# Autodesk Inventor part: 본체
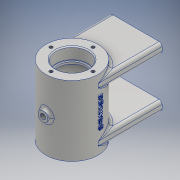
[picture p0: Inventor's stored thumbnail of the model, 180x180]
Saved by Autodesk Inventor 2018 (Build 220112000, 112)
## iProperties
Created: 2020-07
Part Number: 본체
Material: 알루미늄 6061
Document SubType Name: Modeling
Designer: home
Density: 2.7 g/cm^3
Appearance: 알루미늄 - 평지
Mass: 305.056 g
Surface Area: 358.163 cm^2
Volume: 112.984 cm^3
Author: home
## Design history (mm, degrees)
sketch "스케치1"
  geometry: L1 (16, 35)-(16, 23); L2 (16, 23)-(14, 23); L3 (14, 23)-(14, 21); L4 (14, 21)-(21, 21); L5 (21, 21)-(21, -21); L6 (21, -21)-(14, -21); L7 (14, -21)-(14, -23); L8 (14, -23)-(16, -23); L9 (16, -23)-(16, -35); L10 (0, -35)-(0, 35); L11 (16, 35)-(26, 35); L12 (26, 35)-(26, -35); L13 (26, -35)-(16, -35); 3 further points
  constraints: 26 end point, 8 perpendicular, 2 coincident, 2 horizontal, 2 point on line, 2 vertical, 1 midpoint
  dimensions: "d2" = 2 distance of L2.end L3.end; "d4" = 42 distance of L4.end L5.end; "d5" = 2 distance of L6.end L7.end; "d6" = 12 distance of L8.end L9.end; "d8" = 70 distance of L10.start L10.end; "d11" = 32 diameter of L1 L10; "d12" = 52 diameter of L12 L10; "d13" = 42 diameter of L5 L10; "d14" = 10 distance of L12.end L9.end; "d15" = 2 distance of L7.end L8.end; "d16" = 70 distance between parallel lines of L13 L11; "d17" = 35 distance from line of point (0, 0) L11
revolve "회전1" sketch "스케치1" stored, may be unused: angle "d18" = 90 deg
node "작업 평면1"
sketch "스케치2"
  geometry: 1 further point
sketch "스케치3"
  geometry: L1 (-26, -30)-(26, -30); L2 (26, -30)-(26, -20); L3 (26, -20)-(-26, -20); L4 (-26, -20)-(-26, -30); L5 (-26, 35)-(26, 35) reference; L6 (-26, -35)-(26, -35) reference; L7 (-26, 35)-(-26, -35) reference; 1 further point
  constraints: 8 end point, 2 parallel, 1 horizontal, 1 perpendicular
  dimensions: "d20" = 52 distance of L3.end L2.end; "d21" = 10 distance of L2.end L1.end; "d22" = 20 distance from line of L3 point (0, 0); "d23" = 0 distance between parallel lines of L4 L7
extrude "돌출1" join sketch "스케치3" stored distance "d24" = 10; taper "d25" = 0 deg
sketch "스케치4" dims "d26" = 42
  geometry: 3 further points
  constraints: 1 coincident, 1 vertical alignment, 2 other
hole "구멍1" sketch "스케치4" at (0, -21) diameter "d27" = 3.242; stored, may be unused: countersink angle "d31" = 90 deg, drill point angle "d33" = 118 deg; dims "d28" = 8, "d29" = 4, "d30" = 2, "d32" = 10
node "작업 평면2"
sketch "스케치6"
  geometry: C1 r 5 at (0, 0); 1 further point
  constraints: 1 centre point, 1 coincident
  dimensions: "d38" = 10 diameter of C1
extrude "돌출2" join sketch "스케치6" stored distance "d39" = 10 (= d38); taper "d40" = 0 deg
sketch "스케치7"
  geometry: 1 further point
hole "구멍2" sketch "스케치7" at (0, 0) diameter "d41" = 5.188; stored, may be unused: countersink angle "d45" = 90 deg, drill point angle "d47" = 118 deg; dims "d42" = 12, "d43" = 4, "d44" = 2, "d46" = 16
node "작업 평면4"
sketch "스케치11"
  geometry: L1 (-26, -35)-(26, -35) reference; L2 (0, -14.175)-(0, -3.309); L3 (0, -3.309)-(36.054, -3.309); L4 (36.054, -3.309)-(36.054, -14.175); L5 (36.054, -14.175)-(0, -14.175); 1 further point
  constraints: 2 other
  dimensions: "d53" = 35 distance from line of L1 point (0, 0) (derived); "d54" = 26 horizontal distance of L2.end L1.start
feature "엠보싱1" sketch "스케치11" dims "d2" = 2, "d4" = 42, "d5" = 2, "d6" = 12, "d8" = 70, "d11" = 32, "d12" = 52, "d13" = 42, "d14" = 10, "d15" = 2, "d16" = 70, "d17" = 35, "d20" = 52, "d21" = 10, "d22" = 20, "d23" = 0, "d55" = 1, "d56" = 0
fillet "모깎기1" dims "d57" = 3, "d58" = 3, "d59" = 3, "d60" = 0.3, "d61" = 2
chamfer "모따기1" distance "d62" = 1; stored, may be unused: second distance "d63" = 2, angle "d64" = 45 deg
sketch "스케치12"
  geometry: 2 further points
  dimensions: "d65" = 20 horizontal distance of point (3, 5) point (23, 30)
hole "구멍3" sketch "스케치12" at (3, 5) diameter "d66" = 4.134; stored, may be unused: countersink angle "d70" = 90 deg, drill point angle "d72" = 118 deg; dims "d67" = 8, "d68" = 4, "d69" = 2, "d71" = 10
node "솔리드1"
mirror "미러1"
pattern_circular "원형 패턴1" dims angle "d35" = 360 deg
mirror "미러2"
pattern_circular "원형 패턴2" dims angle "d49" = 160 deg
pattern_linear "직사각형 패턴1" dims "d75" = 40, "d78" = 50
node "투영된 루프1"
other parameters: "d19" = 64, "d37" = -29, "d52" = 26
